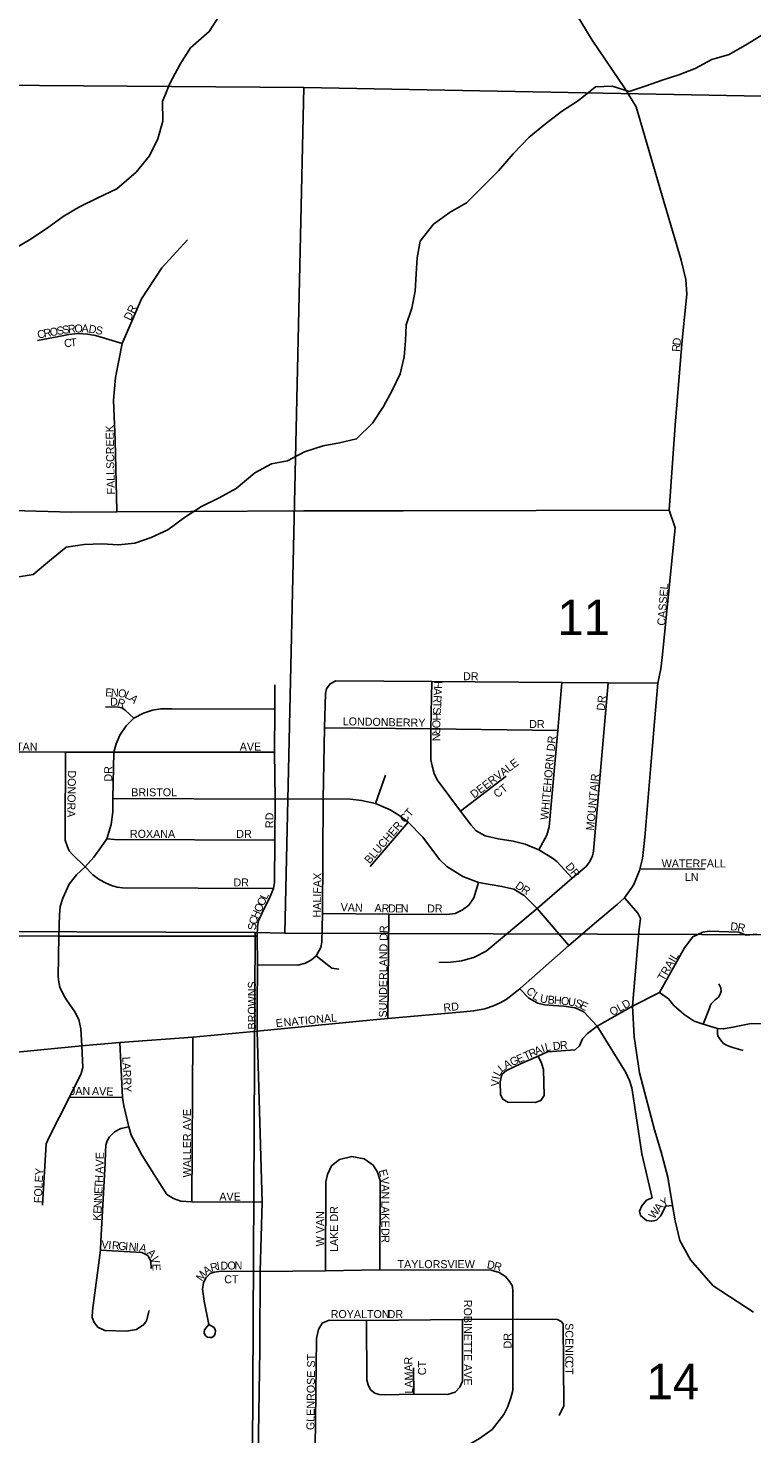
# Model space of a CAD drawing. Extents: x 8.5 to 81.5, y -1.2 to 22.4.
# Drawn here: x 52.966 to 53.822, y 19.27 to 20.934 of the extents above; entities that cross this region are included whole.
import ezdxf

# ---------------------------------------------------------------- set-up
doc = ezdxf.new("R2010")
doc.units = 0
for name, color, linetype in [('GM_P_County_Alignment', 7, 'Continuous'), ('GM_X_City_Street', 7, 'Continuous'), ('GM_X_City_Street_Text', 7, 'Continuous'), ('GM_X_Minor_River', 7, 'Continuous'), ('GM_X_Section', 7, 'Continuous'), ('GM_X_Section_Text', 7, 'Continuous'), ('GM_X_US_Route', 7, 'Continuous')]:
    doc.layers.add(name, color=color, linetype=linetype)

msp = doc.modelspace()

# ---------------------------------------------------------------- linework, layer by layer
at = {"layer": 'GM_P_County_Alignment'}
msp.add_lwpolyline([(53.4097, 20.3625), (53.7244, 20.3633)], dxfattribs=at)
at = {"layer": 'GM_X_City_Street'}
for points in [[(53.7161, 20.1892), (53.7317, 20.3424), (53.7244, 20.3633), (53.7316, 20.464), (53.7397, 20.5648), (53.7453, 20.6189), (53.7442, 20.6364), (53.7386, 20.6593), (53.7162, 20.7356), (53.6853, 20.8406), (53.6725, 20.8621), (53.6334, 20.9195), (53.6033, 20.9694), (53.5739, 21.0311), (53.5332, 21.1219), (53.4927, 21.2165), (53.4786, 21.2506)], [(53.0709, 20.3615), (53.0709, 20.3625), (53.069, 20.4459), (53.0671, 20.4935), (53.0694, 20.5205), (53.0773, 20.5608), (53.1002, 20.6134), (53.1243, 20.6503), (53.1545, 20.6834)], [(52.9771, 20.5642), (53.0022, 20.5691), (53.0141, 20.5714), (53.0247, 20.5725), (53.0362, 20.5719), (53.0459, 20.5703), (53.0773, 20.5608)], [(52.7745, 20.3658), (52.7745, 20.3658), (52.8027, 20.3647), (52.8469, 20.3644), (52.9015, 20.3644), (52.9478, 20.3631), (53.0175, 20.3612), (53.0709, 20.3615), (53.1584, 20.3618), (53.2924, 20.3625), (53.4097, 20.3625)], [(53.7028, 20.0611), (53.7072, 20.1129), (53.7112, 20.1585), (53.7148, 20.1757), (53.7161, 20.1892)], [(53.2372, 19.7749), (53.2376, 19.8253), (53.2371, 19.8591), (53.2376, 19.8711), (53.2386, 19.8774), (53.2446, 19.8906), (53.2512, 19.9034), (53.2563, 19.9158), (53.2575, 19.9228), (53.2578, 19.9729), (53.2582, 20.0214), (53.2574, 20.0772), (53.2581, 20.1278), (53.2579, 20.1569)], [(53.2376, 19.8253), (53.2853, 19.8251), (53.2941, 19.8274), (53.3015, 19.8313), (53.3068, 19.8359), (53.3122, 19.8458), (53.3135, 19.8522), (53.3142, 19.8861), (53.3152, 20.0219), (53.3165, 20.106), (53.3177, 20.1464), (53.3192, 20.1519), (53.3233, 20.158), (53.3302, 20.1616), (53.4438, 20.1608), (53.5973, 20.1595), (53.6523, 20.159), (53.7112, 20.1585)], [(53.4438, 20.1608), (53.4425, 20.1045), (53.4425, 20.068), (53.4441, 20.0609), (53.4463, 20.0518), (53.4499, 20.0444), (53.4777, 20.0073), (53.4902, 19.9906), (53.4962, 19.9841), (53.5067, 19.9779), (53.5223, 19.9745), (53.54, 19.9718), (53.5542, 19.9681), (53.5702, 19.9615), (53.5863, 19.9514), (53.5915, 19.9476), (53.6098, 19.9279)], [(53.4519, 19.8281), (53.4662, 19.8285), (53.4793, 19.8299), (53.4943, 19.8343), (53.5079, 19.8417), (53.5682, 19.8919), (53.6098, 19.9279), (53.6264, 19.9416), (53.6308, 19.9476), (53.6336, 19.9542), (53.635, 19.9597), (53.6523, 20.159)], [(53.5702, 19.9615), (53.5797, 19.9786), (53.5824, 19.9888), (53.5926, 20.1028), (53.5973, 20.1595)], [(52.9832, 19.5409), (52.9873, 19.6134), (52.9908, 19.6212), (53.0151, 19.6688), (53.0287, 19.6967), (53.0308, 19.7039), (53.0296, 19.7295), (53.0285, 19.7494), (53.026, 19.7606), (53.0215, 19.7698), (53.0115, 19.7838), (53.0078, 19.7897), (53.0035, 19.799), (53.0022, 19.805), (53.0016, 19.8111), (53.0023, 19.8594), (53.003, 19.8846), (53.0041, 19.8942), (53.0073, 19.9044), (53.0146, 19.9207), (53.0231, 19.932), (53.0334, 19.9415), (53.0438, 19.9527), (53.0528, 19.9652), (53.0592, 19.9745), (53.0643, 19.9914), (53.0663, 20.0063), (53.0662, 20.022), (53.0676, 20.0771), (53.0701, 20.0868), (53.0745, 20.0971), (53.0819, 20.108), (53.0913, 20.1173), (53.1024, 20.1233), (53.1132, 20.1268), (53.123, 20.1284), (53.136, 20.1282), (53.2581, 20.1278)], [(53.0574, 20.1307), (53.0724, 20.1303), (53.077, 20.1294), (53.0807, 20.1266), (53.0913, 20.1173)], [(52.897, 20.108), (52.8967, 20.0776), (52.896, 19.924), (52.896, 19.9136), (52.8983, 19.903), (52.9031, 19.8916), (52.914, 19.8771), (52.9213, 19.8713), (52.9343, 19.8643), (52.9429, 19.8613), (52.9527, 19.8595), (53.0023, 19.8594), (53.2371, 19.8591)], [(53.3165, 20.106), (53.4425, 20.1045), (53.5926, 20.1028)], [(52.8967, 20.0776), (52.9534, 20.0775), (53.0104, 20.077), (53.0676, 20.0771), (53.2574, 20.0772)], [(53.0104, 20.077), (53.0097, 19.9802), (53.0099, 19.9728), (53.0125, 19.9651), (53.0147, 19.9604), (53.0184, 19.9559), (53.0334, 19.9415), (53.0425, 19.932), (53.05, 19.9264), (53.0582, 19.922), (53.0647, 19.9191), (53.0713, 19.9173), (53.0778, 19.9165), (53.2563, 19.9158)], [(53.3772, 20.0161), (53.3889, 20.05)], [(53.4777, 20.0073), (53.5315, 20.0485)], [(53.6952, 19.9723), (53.6961, 19.9807), (53.7012, 20.0422), (53.7028, 20.0611)], [(53.0662, 20.022), (53.2582, 20.0214), (53.3152, 20.0219), (53.3476, 20.0213), (53.3606, 20.0199), (53.3772, 20.0161), (53.3943, 20.0089), (53.4047, 20.0025), (53.4157, 19.9941), (53.4329, 19.9765), (53.4527, 19.9501), (53.4614, 19.9419), (53.4804, 19.9298), (53.4987, 19.9226), (53.5266, 19.9182), (53.5405, 19.9147), (53.5531, 19.9075), (53.5682, 19.8919), (53.6056, 19.8481)], [(53.3709, 19.9418), (53.4157, 19.9941)], [(53.0592, 19.9745), (53.0683, 19.9735), (53.2578, 19.9729)], [(53.6795, 19.9157), (53.6828, 19.9204), (53.6894, 19.9368), (53.6898, 19.9387), (53.6929, 19.9513), (53.6952, 19.9723)], [(53.6898, 19.9387), (53.7671, 19.9389)], [(53.3142, 19.8861), (53.3928, 19.8852), (53.4616, 19.8848), (53.4711, 19.8862), (53.4798, 19.8906), (53.4874, 19.896), (53.4932, 19.9047), (53.4987, 19.9226)], [(53.8244, 19.4142), (53.7765, 19.4456), (53.7497, 19.4764), (53.7371, 19.4991), (53.7316, 19.5223), (53.7285, 19.5405), (53.7228, 19.574), (53.7148, 19.6052), (53.7072, 19.63), (53.6895, 19.6974), (53.6832, 19.7403), (53.6812, 19.7766), (53.6885, 19.8645), (53.6904, 19.8801), (53.6874, 19.8863), (53.6716, 19.9045), (53.6795, 19.9157)], [(53.3743, 19.7601), (53.3915, 19.7618), (53.481, 19.7696), (53.493, 19.7708), (53.5063, 19.7732), (53.5165, 19.7767), (53.5247, 19.7805), (53.5318, 19.7844), (53.5478, 19.7971), (53.5487, 19.7978), (53.6056, 19.8481), (53.6411, 19.8786), (53.663, 19.8968), (53.6716, 19.9045)], [(53.3915, 19.7618), (53.3928, 19.8852)], [(53.6392, 19.7527), (53.6812, 19.7766), (53.7131, 19.7926), (53.7427, 19.8454), (53.7524, 19.8583), (53.7644, 19.8639), (53.7718, 19.8653), (53.807, 19.8639), (53.8157, 19.8606)], [(53.8157, 19.8606), (53.8281, 19.8618)], [(53.3068, 19.8359), (53.3254, 19.8214), (53.3335, 19.8202)], [(53.7648, 19.7551), (53.772, 19.774), (53.7728, 19.7767), (53.7743, 19.779), (53.779, 19.7838), (53.7828, 19.7869), (53.7849, 19.7905), (53.786, 19.794), (53.7856, 19.7983), (53.7834, 19.8027)], [(53.7285, 19.5405), (53.72, 19.5398), (53.7146, 19.5284), (53.7093, 19.523), (53.7039, 19.5218), (53.6975, 19.5229), (53.6906, 19.5287), (53.6894, 19.534), (53.692, 19.5402), (53.6978, 19.5469), (53.7044, 19.5497), (53.692, 19.6016), (53.6872, 19.636), (53.6804, 19.6797), (53.6774, 19.6883), (53.6731, 19.698), (53.6392, 19.7527), (53.6235, 19.7697), (53.6134, 19.7743), (53.6, 19.7766), (53.5875, 19.7772), (53.5771, 19.7779), (53.5692, 19.78), (53.5586, 19.7858), (53.5478, 19.7971)], [(53.8687, 19.7555), (53.8216, 19.756), (53.7999, 19.7514), (53.7888, 19.7495), (53.7817, 19.7499), (53.7648, 19.7551), (53.7542, 19.7588), (53.7424, 19.7667), (53.7299, 19.7773), (53.7236, 19.7851), (53.7131, 19.7926)], [(53.237, 19.7469), (53.2372, 19.7749)], [(53.237, 19.7469), (53.3743, 19.7601)], [(53.6392, 19.7527), (53.6279, 19.7442), (53.6221, 19.7376), (53.6182, 19.7295), (53.6132, 19.7248), (53.5806, 19.7225), (53.5693, 19.7174), (53.5484, 19.708), (53.5322, 19.7001), (53.5265, 19.6954), (53.5247, 19.6868), (53.5248, 19.6715), (53.5277, 19.6662), (53.5336, 19.6627), (53.5658, 19.6623), (53.5728, 19.6646), (53.5767, 19.6705), (53.5759, 19.7015), (53.5736, 19.7089), (53.5693, 19.7174)], [(53.7817, 19.7499), (53.7816, 19.7436), (53.7821, 19.7413), (53.7841, 19.738), (53.7867, 19.7347), (53.7889, 19.7322), (53.7922, 19.7302), (53.7963, 19.7287), (53.801, 19.7272), (53.8122, 19.7241)], [(53.0747, 19.7333), (53.0777, 19.6684), (53.0792, 19.6584), (53.0853, 19.6338), (53.0878, 19.6239), (53.101, 19.5997), (53.122, 19.5666), (53.1301, 19.5534), (53.1379, 19.5486), (53.1466, 19.5456), (53.1596, 19.545), (53.2431, 19.5445)], [(53.1596, 19.545), (53.1608, 19.7399)], [(53.0151, 19.6688), (53.0777, 19.6684)], [(53.1091, 19.4163), (53.1059, 19.4042), (53.1029, 19.3995), (53.0942, 19.3938), (53.0824, 19.3917), (53.0569, 19.3927), (53.0486, 19.3966), (53.0442, 19.4019), (53.0418, 19.408), (53.0421, 19.4163), (53.0518, 19.4875), (53.0522, 19.4988), (53.0573, 19.5908), (53.0575, 19.6046), (53.0581, 19.6119), (53.0596, 19.6169), (53.0624, 19.6217), (53.0684, 19.6275), (53.0759, 19.6316), (53.0853, 19.6338)], [(53.3177, 19.4633), (53.3182, 19.5685), (53.3204, 19.5773), (53.3248, 19.5875), (53.3345, 19.595), (53.3491, 19.5985)], [(53.3823, 19.4643), (53.3826, 19.57), (53.3795, 19.5798), (53.3742, 19.5882), (53.3636, 19.5957), (53.3491, 19.5985)], [(53.0518, 19.4875), (53.1004, 19.4847), (53.1076, 19.4813), (53.1114, 19.4746), (53.1116, 19.4659)], [(53.1797, 19.3998), (53.1749, 19.3935), (53.1744, 19.3899), (53.1759, 19.3863), (53.1783, 19.3846), (53.1809, 19.3844), (53.1833, 19.3844), (53.186, 19.3861), (53.1874, 19.389), (53.1879, 19.3923), (53.186, 19.3962), (53.1797, 19.3998), (53.1742, 19.4271), (53.1725, 19.4413), (53.1735, 19.4494), (53.1766, 19.4554), (53.1814, 19.46), (53.1862, 19.4616), (53.1944, 19.4626), (53.2404, 19.4624)], [(53.2381, 19.2451), (53.2383, 19.245), (53.2575, 19.2457), (53.2678, 19.2478), (53.2803, 19.2517), (53.2883, 19.2532), (53.3057, 19.2539), (53.4608, 19.2526), (53.4718, 19.2534), (53.4807, 19.2553), (53.4906, 19.2591), (53.5, 19.2646), (53.5151, 19.2755), (53.5287, 19.293), (53.5334, 19.3026), (53.537, 19.3129), (53.5394, 19.3216), (53.5395, 19.4061), (53.5394, 19.439), (53.539, 19.4451), (53.5361, 19.4503), (53.5308, 19.4566), (53.5232, 19.4612)], [(53.2404, 19.4624), (53.3177, 19.4633), (53.3823, 19.4643), (53.514, 19.4638), (53.5232, 19.4612)], [(53.305, 19.189), (53.3057, 19.2539), (53.3073, 19.3832), (53.3095, 19.3938), (53.314, 19.4011), (53.3224, 19.405)], [(53.3224, 19.405), (53.3665, 19.4045), (53.4799, 19.4056), (53.5395, 19.4061), (53.5922, 19.4056)], [(53.3665, 19.4045), (53.3668, 19.3339), (53.3685, 19.3282), (53.371, 19.3225), (53.3764, 19.3186), (53.3815, 19.3169), (53.3877, 19.3163), (53.4223, 19.3174), (53.4623, 19.3169), (53.4711, 19.3197), (53.477, 19.3254), (53.4799, 19.3325), (53.4799, 19.4056)], [(53.5922, 19.4056), (53.5966, 19.4033), (53.5989, 19.4003), (53.5997, 19.3034), (53.5944, 19.2919)], [(53.4223, 19.3174), (53.4218, 19.3483)]]:
    msp.add_lwpolyline(points, dxfattribs=at)
at = {"layer": 'GM_X_Minor_River'}
for points in [[(53.1925, 20.9489), (53.1804, 20.9299), (53.1583, 20.9105), (53.1458, 20.8911), (53.1336, 20.8683), (53.1249, 20.8471), (53.1256, 20.8239), (53.1195, 20.803), (53.1097, 20.7829), (53.0937, 20.7635), (53.0709, 20.7437), (53.0484, 20.7331), (53.0268, 20.7225), (53.0077, 20.7111), (52.9887, 20.697), (52.9678, 20.6834), (52.9484, 20.672)], [(53.8363, 20.9271), (53.8169, 20.9149), (53.7953, 20.9028), (53.7751, 20.8967), (53.7553, 20.8861), (53.7359, 20.8785), (53.7162, 20.8724), (53.6972, 20.8655), (53.677, 20.8591), (53.6572, 20.8652), (53.6374, 20.8644), (53.6173, 20.8481), (53.5971, 20.8352), (53.5781, 20.8207), (53.5587, 20.8048), (53.5401, 20.785), (53.5226, 20.7649), (53.5036, 20.7459), (53.4846, 20.7273), (53.4652, 20.7163), (53.4458, 20.7018), (53.4298, 20.6817), (53.4264, 20.6619), (53.4253, 20.643), (53.4238, 20.6228), (53.42, 20.6023), (53.4135, 20.5829), (53.4127, 20.5639), (53.4108, 20.5449), (53.4063, 20.5248), (53.3971, 20.5058), (53.3865, 20.486), (53.3736, 20.4663), (53.3546, 20.4477), (53.3344, 20.4431), (53.315, 20.4397), (53.293, 20.4325), (53.2728, 20.4219), (53.2538, 20.4181), (53.2344, 20.4078), (53.212, 20.3892), (53.1922, 20.3782), (53.1713, 20.3676), (53.1511, 20.3547), (53.1314, 20.3402), (53.1116, 20.3311), (53.0922, 20.3243), (53.0728, 20.3224), (53.0534, 20.3235), (53.0325, 20.3228), (53.0112, 20.3198), (52.9914, 20.3034), (52.972, 20.2871), (52.9526, 20.2841)]]:
    msp.add_lwpolyline(points, dxfattribs=at)
at = {"layer": 'GM_X_Section'}
for points in [[(52.2493, 20.8716), (53.2922, 20.8638), (53.2697, 19.8629), (53.2345, 19.8635), (52.284, 19.8673), (52.2803, 20.0166)], [(52.284, 19.8673), (53.2345, 19.8635), (53.2294, 18.8627), (52.2136, 18.8983), (52.2219, 19.2023)], [(53.2345, 19.8635), (53.2697, 19.8629), (54.1332, 19.86), (54.1387, 19.8542), (54.1465, 19.845), (54.1513, 19.8385), (54.1598, 19.8273), (54.1654, 19.8204), (54.1691, 19.8165), (54.1807, 19.8076), (54.1866, 19.8022), (54.2077, 19.7764), (54.2144, 19.7672), (54.2299, 19.7453), (54.2329, 18.8542), (53.2294, 18.8627)]]:
    msp.add_lwpolyline(points, close=True, dxfattribs=at)
msp.add_lwpolyline([(54.1332, 19.86), (53.2697, 19.8629), (53.2922, 20.8638), (53.9801, 20.8506)], dxfattribs=at)
at = {"layer": 'GM_X_US_Route'}
for points in [[(53.0425, 19.7306), (53.0747, 19.7333), (53.1608, 19.7399), (53.237, 19.7469)], [(53.237, 19.7469), (53.2431, 19.5445), (53.2404, 19.4624), (53.2402, 19.376)], [(52.643, 19.6938), (52.654, 19.6948), (52.7125, 19.6992), (52.7729, 19.706), (52.8476, 19.7116), (52.9162, 19.7184), (53.0296, 19.7295), (53.0425, 19.7306)], [(53.2402, 19.376), (53.2402, 19.3698), (53.2381, 19.2451), (53.238, 19.1895), (53.2372, 19.0463)]]:
    msp.add_lwpolyline(points, dxfattribs=at)

# ---------------------------------------------------------------- texts
at = {"layer": 'GM_X_City_Street_Text'}
for s, rotation, p in [('DR', 64.7982, (53.0873, 20.5871)), ('S', 10.383, (53.0007, 20.5706)), ('S', 10.0507, (53.0073, 20.5718)), ('R', 5.278, (53.0136, 20.573)), ('O', 2.0111, (53.021, 20.5736)), ('A', 357.9452, (53.0291, 20.5739)), ('D', 350.4694, (53.0371, 20.5737)), ('S', 349.2528, (53.0453, 20.5723)), ('C', 10.3765, (52.9778, 20.5664)), ('R', 10.3765, (52.9852, 20.5678)), ('O', 10.3966, (52.9925, 20.5691)), ('C', 6.5226, (53.0091, 20.5561)), ('T', 5.0609, (53.0164, 20.5569)), ('D', 82.9671, (53.7377, 20.5579)), ('R', 85.8919, (53.7372, 20.5506)), ('CREEK', 91.2447, (53.068, 20.4205)), ('FALLS', 91.3632, (53.0688, 20.3821)), ('CASSEL', 85.5997, (53.7197, 20.2265)), ('DR', 0, (53.4806, 20.1622)), ('E', 358.1145, (53.0572, 20.1431)), ('N', 358.0981, (53.0639, 20.1429)), ('O', 352.1512, (53.0719, 20.1426)), ('L', 335.4882, (53.0795, 20.1417)), ('A', 267.4933, (53.4462, 20.1529)), ('H', 267.4858, (53.4466, 20.1613)), ('D', 359.6284, (53.0631, 20.132)), ('R', 343.5776, (53.0707, 20.132)), ('A', 318.9128, (53.085, 20.1393)), ('T', 267.5048, (53.4455, 20.1371)), ('R', 267.4735, (53.4458, 20.1446)), ('DR', 83.9946, (53.648, 20.1257)), ('LONDONBERRY', 358.9094, (53.3382, 20.1089)), ('O', 267.5834, (53.4445, 20.1154)), ('H', 267.4858, (53.4449, 20.1238)), ('S', 267.5048, (53.4452, 20.1304)), ('DR', 0, (53.5589, 20.1056)), ('R', 269.0792, (53.4442, 20.1068)), ('N', 269.9478, (53.4441, 20.0992)), ('SPARTAN', 0, (52.9173, 20.0789)), ('AVE', 0, (53.2164, 20.0789)), ('WHITEHORN DR', 84.6595, (53.5813, 19.9965)), ('DEERVALE', 37.1827, (53.4937, 20.0219)), ('DONORA', 269.0295, (53.0132, 20.0555)), ('DR', 90, (53.0655, 20.0422)), ('MOUNTAIR', 84.6676, (53.6355, 19.984)), ('BRISTOL', 0, (53.0881, 20.0248)), ('CT', 38.1614, (53.5212, 20.0224)), ('RD', 90, (53.2563, 19.9872)), ('BLUCHER CT', 49.255, (53.3701, 19.9442)), ('ROXANA', 0, (53.0865, 19.9756)), ('DR', 0, (53.2123, 19.9756)), ('WATERFALL', 0, (53.7156, 19.9406)), ('HALIFAX', 89.0778, (53.3123, 19.8813)), ('DR', 308.6634, (53.6012, 19.9416)), ('LN', 0, (53.7431, 19.9245)), ('DR', 0, (53.209, 19.9181)), ('D', 326.4373, (53.5416, 19.917)), ('R', 327.4902, (53.5487, 19.9123)), ('O', 65.8295, (53.2448, 19.8943)), ('L', 65.8183, (53.2482, 19.9019)), ('VAN', 358.0918, (53.3357, 19.8889)), ('C', 72.7401, (53.2359, 19.8722)), ('H', 66.0752, (53.238, 19.8791)), ('O', 65.8111, (53.2414, 19.8867)), ('A', 357.3111, (53.3757, 19.8881)), ('R', 357.5341, (53.3841, 19.8877)), ('D', 359.272, (53.3919, 19.8874)), ('E', 359.9707, (53.4003, 19.8873)), ('N', 359.9929, (53.407, 19.8873)), ('DR', 0, (53.4381, 19.8873)), ('S', 86.0078, (53.2355, 19.8662)), ('SUNDERLAND DR', 89.5087, (53.3905, 19.763)), ('D', 354.3742, (53.7965, 19.8664)), ('R', 348.0375, (53.8046, 19.8657)), ('TRAIL', 59.7432, (53.7182, 19.8056)), ('BROWNS', 90, (53.2355, 19.7488)), ('C', 310.1009, (53.5546, 19.794)), ('L', 328.7204, (53.562, 19.7861)), ('U', 348.9204, (53.571, 19.7813)), ('B', 355.6401, (53.5804, 19.7796)), ('H', 355.5141, (53.5879, 19.779)), ('O', 354.3307, (53.5961, 19.7783)), ('U', 351.1774, (53.6043, 19.7775)), ('S', 340.5024, (53.6121, 19.7764)), ('E', 335.0112, (53.6181, 19.7742)), ('OLD', 29.2472, (53.6572, 19.7645)), ('NATIONAL', 5.5528, (53.2688, 19.7523)), ('RD', 6.0168, (53.4579, 19.7698)), ('E', 7.1217, (53.2596, 19.7514)), ('L', 11.4117, (53.5785, 19.7229)), ('D', 5.1212, (53.5873, 19.7244)), ('R', 5.0823, (53.5956, 19.7252)), ('LARRY', 272.4355, (53.0774, 19.7164)), ('G', 24.0912, (53.5386, 19.7053)), ('E', 24.0235, (53.5462, 19.7087)), ('T', 24.0513, (53.5546, 19.7124)), ('R', 24.034, (53.5607, 19.7151)), ('A', 24.0424, (53.5675, 19.7182)), ('I', 21.5335, (53.5751, 19.7215)), ('L', 61.8343, (53.524, 19.6926)), ('L', 39.2913, (53.5266, 19.6977)), ('A', 26.5357, (53.5313, 19.7016)), ('V', 86.3473, (53.523, 19.6812)), ('I', 78.7843, (53.5235, 19.6892)), ('JAN', 0, (53.0156, 19.6714)), ('AVE', 358.0261, (53.0415, 19.6714)), ('WALLER AVE', 90, (53.1588, 19.5738)), ('E', 89.9457, (53.0555, 19.5952)), ('FOLEY', 87.4567, (52.9822, 19.5431)), ('A', 87.2227, (53.0549, 19.578)), ('V', 88.6528, (53.0553, 19.5866)), ('E', 285.5475, (53.3807, 19.5818)), ('T', 87.2126, (53.054, 19.5605)), ('H', 87.2009, (53.0544, 19.5672)), ('V', 276.9027, (53.383, 19.5734)), ('A', 270.3061, (53.384, 19.5654)), ('N', 87.2009, (53.0533, 19.5456)), ('E', 87.2253, (53.0537, 19.5539)), ('AVE', 0, (53.1923, 19.5464)), ('N', 270, (53.3841, 19.5571)), ('Y', 28.6767, (53.7175, 19.5385)), ('E', 87.2126, (53.0526, 19.5306)), ('N', 87.2117, (53.0529, 19.5372)), ('W VAN', 90, (53.3163, 19.4922)), ('LAKE DR', 90, (53.3326, 19.4855)), ('L', 269.9956, (53.3841, 19.5462)), ('A', 269.9928, (53.3841, 19.5396)), ('W', 52.4509, (53.7066, 19.5239)), ('A', 52.4394, (53.7132, 19.5325)), ('K', 87.2227, (53.0522, 19.5223)), ('K', 269.9928, (53.3841, 19.5313)), ('E', 269.9956, (53.3841, 19.5229)), ('V', 355.6901, (53.0524, 19.4898)), ('D', 269.9928, (53.3841, 19.5138)), ('R', 269.994, (53.3841, 19.5054)), ('I', 355.6795, (53.0607, 19.4892)), ('R', 355.6739, (53.0649, 19.4888)), ('G', 355.6915, (53.0723, 19.4883)), ('I', 355.6983, (53.0806, 19.4876)), ('N', 355.6901, (53.0848, 19.4873)), ('I', 355.6683, (53.0931, 19.4867)), ('A', 346.3878, (53.0969, 19.4865)), ('A', 312.3104, (53.1059, 19.484)), ('V', 285.0328, (53.1109, 19.4789)), ('E', 272.0493, (53.113, 19.4714)), ('A', 32.8836, (53.1766, 19.4578)), ('R', 15.1848, (53.1829, 19.462)), ('I', 8.909, (53.1899, 19.4639)), ('D', 1.7052, (53.1937, 19.4645)), ('O', 0.0219, (53.2019, 19.4648)), ('N', 0, (53.2103, 19.4648)), ('TAYLORSVIEW', 0, (53.4031, 19.4664)), ('D', 349.3374, (53.5083, 19.4664)), ('R', 345.4925, (53.5163, 19.4649)), ('M', 54.1976, (53.1714, 19.4503)), ('CT', 0, (53.1981, 19.4485)), ('ROYALTON', 0, (53.324, 19.4073)), ('DR', 0, (53.3914, 19.4073)), ('ROBINETTE AVE', 270, (53.4816, 19.4288)), ('SCENIC', 270, (53.6016, 19.4013)), ('DR', 90, (53.538, 19.3713)), ('GLENROSE ST', 89.3776, (53.3047, 19.2747)), ('LAMAR', 91.1451, (53.4213, 19.318)), ('CT', 90, (53.4368, 19.3397)), ('CT', 270, (53.6016, 19.3572))]:
    msp.add_text(s, height=0.00947, rotation=rotation, dxfattribs=at).set_placement(p)
at = {"layer": 'GM_X_Section_Text'}
for s, p in [('11', (53.5923, 20.2156)), ('14', (53.6977, 19.3113))]:
    msp.add_text(s, height=0.04186, rotation=0, dxfattribs=at).set_placement(p)

doc.saveas('drawing.dxf')
